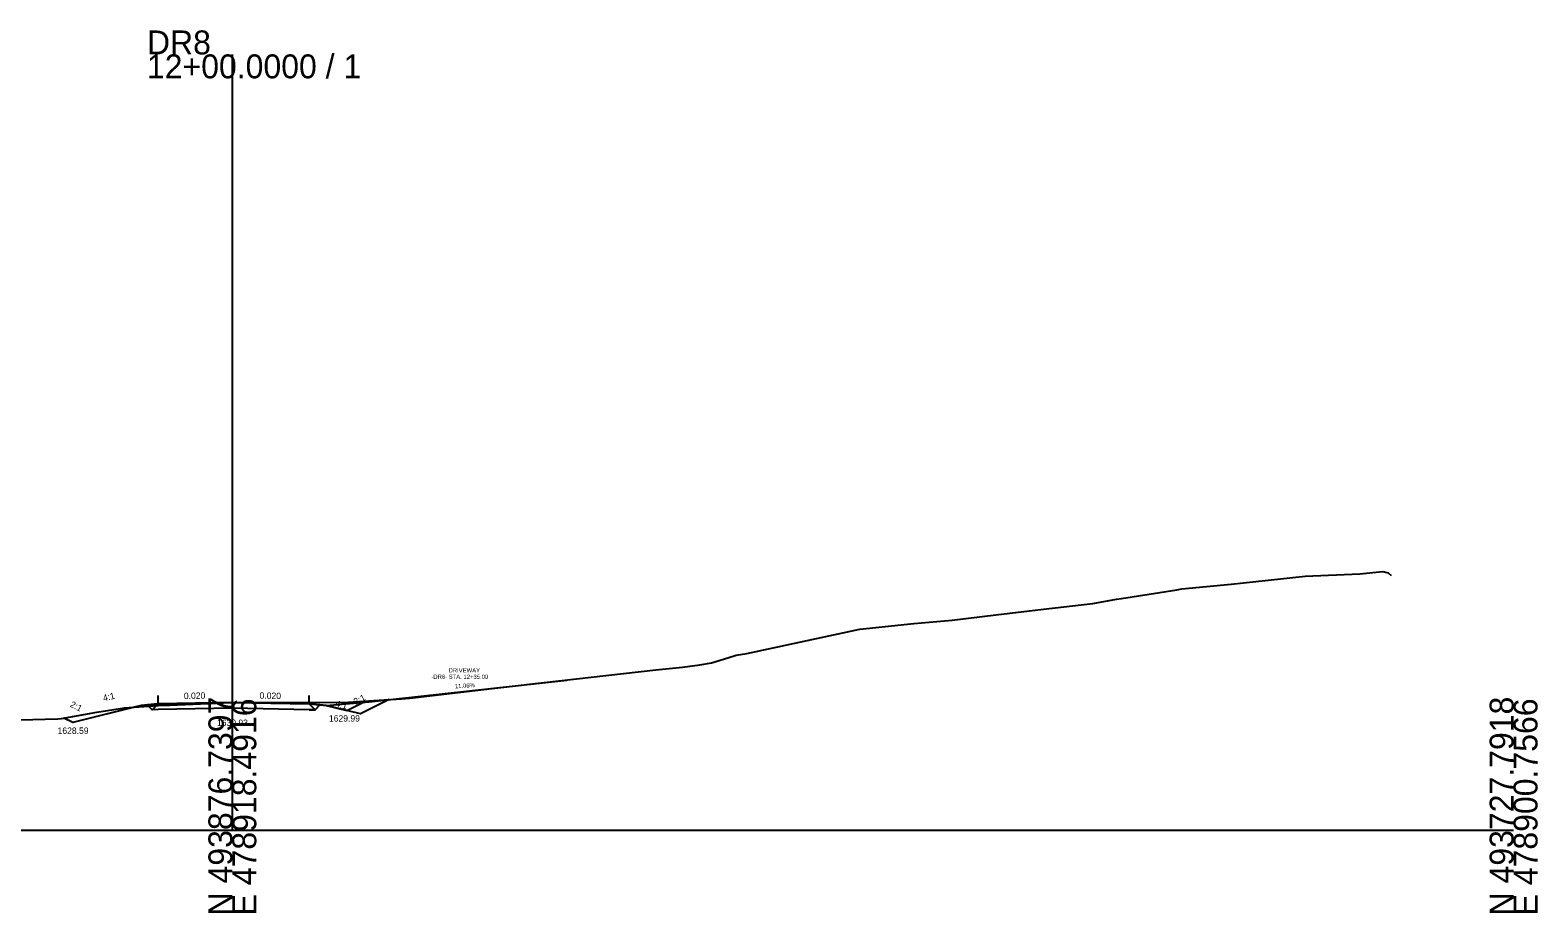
# Model space of a CAD drawing. Extents: x 24 to 353, y -10 to 3552.
# Drawn here: x 176.3 to 352.8, y 1990.3 to 2093.6 of the extents above; entities that cross this region are included whole.
import ezdxf

# ---------------------------------------------------------------- set-up
doc = ezdxf.new("R2010")
doc.units = 0
for name, color, linetype in [('Exist Cross Section Cell', 7, 'Continuous'), ('Exist XS Center Line Elevation Label', 7, 'Continuous'), ('Exist XS Ground Line', 7, 'Continuous'), ('Pattern 3', 7, 'Continuous'), ('Prop XS Ditch Slope Text', 7, 'Continuous'), ('Prop XS Ditch Standard Text', 7, 'Continuous'), ('Prop XS Dump Level', 7, 'Continuous'), ('Prop XS Earthwork Shape', 7, 'Continuous'), ('Prop XS EOT Tick Mark', 7, 'Continuous'), ('Prop XS Finish Grade', 7, 'Continuous'), ('Prop XS Finish Grade Earthwork', 7, 'Continuous'), ('Prop XS Finish Grade Pavement', 7, 'Continuous'), ('Prop XS Hydro Typical Ditch Data', 7, 'Continuous'), ('Prop XS Pvmt Edge Slope', 7, 'Continuous'), ('Prop XS SE Text', 7, 'Continuous'), ('Prop XS Shoulder Borrow Shape', 7, 'Continuous'), ('Prop XS Side Slope Text', 7, 'Continuous'), ('Prop XS Subgrade Earthwork', 7, 'Continuous'), ('Scratch_Level_5', 7, 'Continuous')]:
    doc.layers.add(name, color=color, linetype=linetype)

msp = doc.modelspace()

# ---------------------------------------------------------------- linework, layer by layer
at = {"layer": 'Exist Cross Section Cell'}
for p, q in [((200, 2000), (200, 2090.78)), ((50, 2000), (200, 2000)), ((200, 2000), (350, 2000))]:
    msp.add_line(p, q, dxfattribs=at)
at = {"layer": 'Exist XS Ground Line'}
msp.add_lwpolyline([(169.34, 2012.74), (178.07, 2012.97), (179.57, 2013.01), (179.98, 2013.06), (184.12, 2013.78), (187.38, 2014.32), (191.31, 2014.58), (192.69, 2014.63), (199.85, 2014.93), (204.46, 2014.91), (209.08, 2014.94), (213.6, 2014.96), (219.79, 2015.36), (220.27, 2015.38), (220.76, 2015.44), (231.1, 2016.63), (233.84, 2016.96), (234.44, 2017.02), (249.59, 2018.73), (252.72, 2019.08), (254.73, 2019.34), (256.09, 2019.55), (258.02, 2020.17), (259, 2020.46), (260.25, 2020.68), (273.48, 2023.52), (279.78, 2024.18), (284.28, 2024.57), (289.39, 2025.19), (294.97, 2025.85), (300.74, 2026.51), (303.53, 2027.01), (304.1, 2027.11), (310.57, 2028.1), (311.15, 2028.22), (316.94, 2028.79), (325.58, 2029.7), (332, 2029.99), (334.71, 2030.26), (335.3, 2030.1), (335.67, 2029.78)], dxfattribs=at)
at = {"layer": 'Pattern 3'}
for p, q in [((216, 2014.99), (239.17, 2017.55)), ((211, 2014.59), (216, 2014.99))]:
    msp.add_line(p, q, dxfattribs=at)
at = {"layer": 'Prop XS Dump Level'}
for p, q in [((200, 2014.93), (191.31, 2014.75)), ((209, 2014.75), (200, 2014.93))]:
    msp.add_line(p, q, dxfattribs=at)
at = {"layer": 'Prop XS Earthwork Shape'}
for points in [[(188.49, 2014.39), (181.31, 2012.59), (180.28, 2013.11), (184.12, 2013.78), (187.38, 2014.32)], [(190.2, 2014.5), (190.05, 2014.65), (189.31, 2014.59), (188.49, 2014.39)], [(190.2, 2014.5), (191.31, 2014.58), (192.69, 2014.63), (199.85, 2014.93), (204.46, 2014.91), (209.08, 2014.94), (213.6, 2014.96), (218.36, 2015.27), (215, 2013.59), (211, 2014.59), (210.26, 2014.65), (209.68, 2014.07), (209, 2014.08), (200, 2014.26), (191.31, 2014.09), (190.63, 2014.07)]]:
    msp.add_lwpolyline(points, close=True, dxfattribs=at)
at = {"layer": 'Prop XS EOT Tick Mark'}
for p, q in [((191.31, 2014.75), (191.31, 2015.75)), ((209, 2014.75), (209, 2015.75))]:
    msp.add_line(p, q, dxfattribs=at)
at = {"layer": 'Prop XS Finish Grade'}
for p, q in [((191.31, 2014.75), (190.05, 2014.65)), ((209, 2014.75), (210.26, 2014.65))]:
    msp.add_line(p, q, dxfattribs=at)
at = {"layer": 'Prop XS Finish Grade Earthwork'}
for p, q in [((189.31, 2014.59), (181.31, 2012.59)), ((190.05, 2014.65), (189.31, 2014.59)), ((210.26, 2014.65), (211, 2014.59)), ((211, 2014.59), (213.39, 2013.99)), ((213.39, 2013.99), (215.59, 2015.09)), ((181.31, 2012.59), (180.28, 2013.11))]:
    msp.add_line(p, q, dxfattribs=at)
at = {"layer": 'Prop XS Finish Grade Pavement'}
for p, q in [((191.31, 2014.75), (200, 2014.93)), ((200, 2014.93), (209, 2014.75))]:
    msp.add_line(p, q, dxfattribs=at)
at = {"layer": 'Prop XS Hydro Typical Ditch Data'}
for p, q in [((189.31, 2014.59), (181.31, 2012.59)), ((181.31, 2012.59), (180.28, 2013.11))]:
    msp.add_line(p, q, dxfattribs=at)
at = {"layer": 'Prop XS Pvmt Edge Slope'}
for p, q in [((191.31, 2014.75), (190.63, 2014.07)), ((209, 2014.75), (209.68, 2014.07))]:
    msp.add_line(p, q, dxfattribs=at)
at = {"layer": 'Prop XS Shoulder Borrow Shape'}
for points in [[(191.31, 2014.75), (190.63, 2014.07), (190.05, 2014.65)], [(191.31, 2014.75), (190.63, 2014.07), (190.05, 2014.65)], [(191.31, 2014.75), (190.63, 2014.07), (190.05, 2014.65)], [(209.68, 2014.07), (210.26, 2014.65), (209, 2014.75)], [(209.68, 2014.07), (210.26, 2014.65), (209, 2014.75)], [(209.68, 2014.07), (210.26, 2014.65), (209, 2014.75)]]:
    msp.add_lwpolyline(points, close=True, dxfattribs=at)
at = {"layer": 'Prop XS Subgrade Earthwork'}
for p, q in [((190.63, 2014.07), (190.05, 2014.65)), ((191.31, 2014.09), (190.63, 2014.07)), ((200, 2014.26), (191.31, 2014.09)), ((209, 2014.08), (200, 2014.26)), ((209, 2014.08), (209.68, 2014.07)), ((209.68, 2014.07), (210.26, 2014.65))]:
    msp.add_line(p, q, dxfattribs=at)
at = {"layer": 'Scratch_Level_5'}
msp.add_lwpolyline([(169.34, 2012.74), (178.07, 2012.97), (179.57, 2013.01), (179.98, 2013.06), (184.12, 2013.78), (187.38, 2014.32), (191.31, 2014.58), (192.69, 2014.63), (199.85, 2014.93), (204.46, 2014.91), (209.08, 2014.94), (213.6, 2014.96), (219.79, 2015.36), (220.27, 2015.38), (220.76, 2015.44), (231.1, 2016.63), (233.84, 2016.96), (234.44, 2017.02), (249.59, 2018.73), (252.72, 2019.08), (254.73, 2019.34), (256.09, 2019.55), (258.02, 2020.17), (259, 2020.46), (260.25, 2020.68), (273.48, 2023.52), (279.78, 2024.18), (284.28, 2024.57), (289.39, 2025.19), (294.97, 2025.85), (300.74, 2026.51), (303.53, 2027.01), (304.1, 2027.11), (310.57, 2028.1), (311.15, 2028.22), (316.94, 2028.79), (325.58, 2029.7), (332, 2029.99), (334.71, 2030.26), (335.3, 2030.1), (335.67, 2029.78)], dxfattribs=at)

# ---------------------------------------------------------------- texts
at = {"layer": 'Exist Cross Section Cell'}
for s, p in [('DR8', (190, 2090.78)), ('12+00.0000 / 1', (190, 2087.98))]:
    msp.add_text(s, height=2.8, dxfattribs=at).set_placement(p)
for s, p in [('N 493876.7397', (200, 1990)), ('E 478918.4916', (202.8, 1990)), ('N 493727.7918', (350, 1990)), ('E 478900.7566', (352.8, 1990))]:
    msp.add_text(s, height=2.8, rotation=90, dxfattribs=at).set_placement(p)
at = {"layer": 'Exist XS Center Line Elevation Label'}
msp.add_text('1630.93', height=0.75, dxfattribs=at).set_placement((198.2, 2012.18))
at = {"layer": 'Pattern 3'}
for s, p in [('-DR8- STA. 12+35.00', (223.3, 2017.69)), ('DRIVEWAY', (225.31, 2018.44))]:
    msp.add_text(s, height=0.5, dxfattribs=at).set_placement(p)
msp.add_text('11.06%', height=0.5, rotation=3.868, dxfattribs=at).set_placement((226.06, 2016.57))
at = {"layer": 'Prop XS Ditch Slope Text'}
for rotation, p in [(14.0348, (184.95, 2015.05)), (345.9638, (212, 2014.47))]:
    msp.add_text('4:1', height=0.75, rotation=rotation, dxfattribs=at).set_placement(p)
at = {"layer": 'Prop XS Ditch Standard Text'}
for s, p in [('1629.99', (211.31, 2012.69)), ('1628.59', (179.54, 2011.25))]:
    msp.add_text(s, height=0.75, dxfattribs=at).set_placement(p)
at = {"layer": 'Prop XS Dump Level'}
for p in [(189.31, 2014.55), (211, 2014.55)]:
    msp.add_text('Case1', height=0.04, dxfattribs=at).set_placement(p)
at = {"layer": 'Prop XS SE Text'}
for rotation, p in [(1.1458, (194.33, 2015.32)), (358.8542, (203.18, 2015.37))]:
    msp.add_text('0.020', height=0.75, rotation=rotation, dxfattribs=at).set_placement(p)
at = {"layer": 'Prop XS Side Slope Text'}
for rotation, p in [(26.5651, (214.43, 2014.64)), (333.4373, (180.93, 2014.46))]:
    msp.add_text('2:1', height=0.75, rotation=rotation, dxfattribs=at).set_placement(p)

doc.saveas('drawing.dxf')
